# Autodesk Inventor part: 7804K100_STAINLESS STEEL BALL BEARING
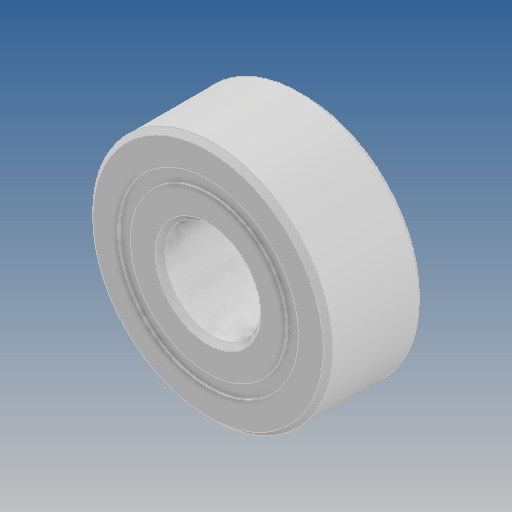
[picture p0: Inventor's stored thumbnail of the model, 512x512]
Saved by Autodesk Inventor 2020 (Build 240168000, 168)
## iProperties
Created: 2017-07
Part Number: 7804K100_STAINLESS STEEL BALL BEARING
Material: Generic
Description: STEP AP203
Document SubType Name: Modeling
Designer: yello
Density: 1 g/cm^3
Appearance: Default
Title: 7804K1.STEP
Revision Number: ANY
Sending System: SolidWorks 2016
Preprocessor: SwSTEP 2.0
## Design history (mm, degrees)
feature "Revolve1"
feature "Revolve3"
feature "Revolve4"
feature "CirPattern1[1]" [Revolve]
feature "CirPattern1[2]" [Revolve]
feature "CirPattern1[3]" [Revolve]
feature "CirPattern1[4]" [Revolve]
feature "CirPattern1[5]" [Revolve]
feature "CirPattern1[6]" [Revolve]
feature "CirPattern1[7]" [Revolve]
feature "CirPattern1[8]" [Revolve]
feature "CirPattern1[9]" [Revolve]
feature "CirPattern1[10]" [Revolve]
feature "CirPattern1[11]" [Revolve]
feature "Revolve5[1]"
feature "Revolve5[2]"
body "Solid1"
body "Solid2"
body "Solid3"
body "Solid4"
body "Solid5"
body "Solid6"
body "Solid7"
body "Solid8"
body "Solid9"
body "Solid10"
body "Solid11"
body "Solid12"
body "Solid13"
body "Solid14"
body "Solid15"
body "Solid16"
